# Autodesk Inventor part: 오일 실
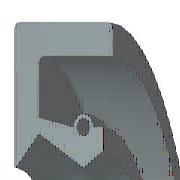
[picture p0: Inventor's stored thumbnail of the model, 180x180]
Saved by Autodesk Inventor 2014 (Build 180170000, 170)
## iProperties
IsCustomPart: 0
Created: 2014-10
Part Number: 오일 실
Material: 고무
Description: 오일-실
Document SubType Name: Modeling
Standard: KS B 2804
Designer: KYOUNG IL JANG
Standards Organization: KS
Language: ko-KR
Size Designation: D - 17 32 8
Categories: <MemberInstance><Categories><Category DisplayName="샤프트 부품" InternalName="7f7aeb1f-a693-4053-b835-cee3144e0d98" Mnemonic="SHFT"><Category DisplayName="실링" Intern
Density: 0.93 g/cm^3
Mass: 2.28027 g
Surface Area: 32.1224 cm^2
Volume: 2.45191 cm^3
Appearance: 고무 - 검은색 - 버전 1.1
Author: SeoGD™ [www.esajin.kr]
Revision Number: 1
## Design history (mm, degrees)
revolve "본체" stored, may be unused: angle "d17" = 90 deg
revolve "스프링1" stored, may be unused: angle "d18" = 90 deg
body "Solid1"
sketch "스케치1"
  geometry: L1 (0, 16)-(8, 16); L2 (8, 14.25)-(1.75, 14.25); L3 (1.75, 10.25)-(4.9, 8.5); L4 (4.9, 8.5)-(0, 8.5); L5 (0, 0)-(9.586, 0) reference; L6 (4.9, 8.5)-(6.3, 9.375); L7 (0, 18)-(0, -3) reference; L8 (-1.941, 0)-(11.507, 0) reference; L9 (4.2, 10.6)-(1.75, 11.21); L10 (1.75, 11.21)-(1.75, 14.25); L11 (0, 16)-(0, 8.588); L12 (4.9, 8.5)-(0, 8.5); L13 (1.75, 10.25)-(0.152, 8.528); L14 (8, 16)-(8, 14.25); L15 (5.6, 10.6)-(6.3, 10.6); L16 (6.3, 10.6)-(6.3, 9.375); C1 r 0.455 at (4.9, 10.6); A1 r 0.7 centre (4.9, 10.6) between (5.6, 10.6) and (4.2, 10.6); A2 r 0.088 centre (0.088, 8.588) between (0, 8.588) and (0.152, 8.528); 1 further point
  constraints: 28 end point, 5 horizontal alignment, 5 point on line, 4 point on circle, 4 vertical alignment, 3 centre point, 3 tangent, 2 collinear, 2 horizontal, 2 perpendicular, 1 coincident, 1 parallel
  dimensions: "d0" = 32 diameter of L1 L5 (= SD2); "d1" = 1.75 distance of L1.end L2.start (= SD); "d2" = 0.91 diameter of C1 (= SPDI); "d3" = 1.4 diameter of A1 (= SPDA); "d4" = 17 diameter of L3.end L5 (= NND); "d5" = 20.5 diameter of L3.start L5 (= TKDM); "d7" = 22.42 diameter of L9.end L5 (= TKDM + 0.24 x SWDT); "d8" = 1.75 distance between parallel lines of L11 L10 (= SD); "d9" = 4.9 distance from line of L11 C1.centre (= SPDST); "d10" = 21.2 diameter of C1.centre L5 (= HLDM); "d11" = 0.0875 radius of A2 (= 0.25 x LAB); "d12" = 6.3 distance between parallel lines of L11 L16 (= SDI); "d13" = 18.75 diameter of L6.end L5 (= ABDM); "d14" = 8 distance from line of L11 L1.end (= SWDT)
fillet "모깎기1" dims "d6" = 0.3 (= RR)
other parameters: "SD2" = 32 [user parameter; used in 1 equation term], "SWDT" = 8 [user parameter; used in 2 equation terms], "RR" = 0.3 [user parameter; used in 1 equation term], "SD" = 1.75 [user parameter; used in 2 equation terms], "NND" = 17 [user parameter; used in 1 equation term], "SPDA" = 1.4 [user parameter; used in 1 equation term], "SPDI" = 0.91 [user parameter; used in 1 equation term], "TKDM" = 20.5 [user parameter; used in 2 equation terms], "HLDM" = 21.2 [user parameter; used in 1 equation term], "ABDM" = 18.75 [user parameter; used in 1 equation term], "SDI" = 6.3 [user parameter; used in 1 equation term], "SPDST" = 4.9 [user parameter; used in 1 equation term], "LAB" = 0.35 [user parameter; used in 1 equation term], "d15" = 0, "d16" = 0, "d19" = 0
